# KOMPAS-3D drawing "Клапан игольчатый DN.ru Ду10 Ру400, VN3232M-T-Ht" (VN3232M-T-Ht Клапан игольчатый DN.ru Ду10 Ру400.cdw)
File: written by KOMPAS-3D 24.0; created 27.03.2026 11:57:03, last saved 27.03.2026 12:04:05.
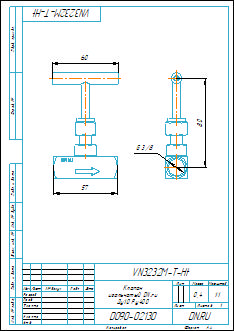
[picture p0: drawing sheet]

Document properties: Автор: Илья; Форматы листов документа: A4; Полное имя файла: VN3232M-T-Ht Клапан игольчатый DN.ru Ду10 Ру400.m3d; Масса: 0.4; Наименование: Клапан игольчатый DN.ru Ду10 Ру400; Количество листов документа: 1; Примечание: D090-02130

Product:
- Body: Body3  | qty 1
    Масса: 0.224966
- Part/product: Клапан игольчатый DN.ru Ду10 Ру400  | designation VN3232M-T-Ht
    Масса: 0.4
    Раздел спецификации: Прочие изделия
    Примечание: D090-02130

Views: Вид 1, Слева, Проекционный вид 2
Referenced files in D:\Обмен\Заказы с фриланса\DN.ru\VNxxM-T-Ht Клапан игольчатый DN.ru Ду8-50 Ру400\VN3232M-T-Ht Клапан игольчатый DN.ru Ду8-50 Ру400\DN8\: VN3232M-T-Ht Клапан игольчатый DN.ru Ду8 Ру400.m3d, VN3232M-T-Ht Клапан игольчатый DN.ru Ду8 Ру400.cdw
Referenced files in D:\Обмен\Заказы с фриланса\DN.ru\VNxxM-T-Ht Клапан игольчатый DN.ru Ду8-50 Ру400\VN3232M-T-Ht Клапан игольчатый DN.ru Ду8-50 Ру400\DN10\: VN3232M-T-Ht Клапан игольчатый DN.ru Ду10 Ру400.m3d
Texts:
  VN3232M-T-Ht
  Клапан
  игольчатый DN.ru
  Ду10 Ру400
  Body3
  Клапан игольчатый DN.ru Ду10 Ру400
  VN3232M-T-Ht Клапан игольчатый DN.ru Ду10 Ру400
Dimensions and other numbers on the sheet: 0; 3; 2; 4; 57; 60; 80; 1:1; 1; 0,4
